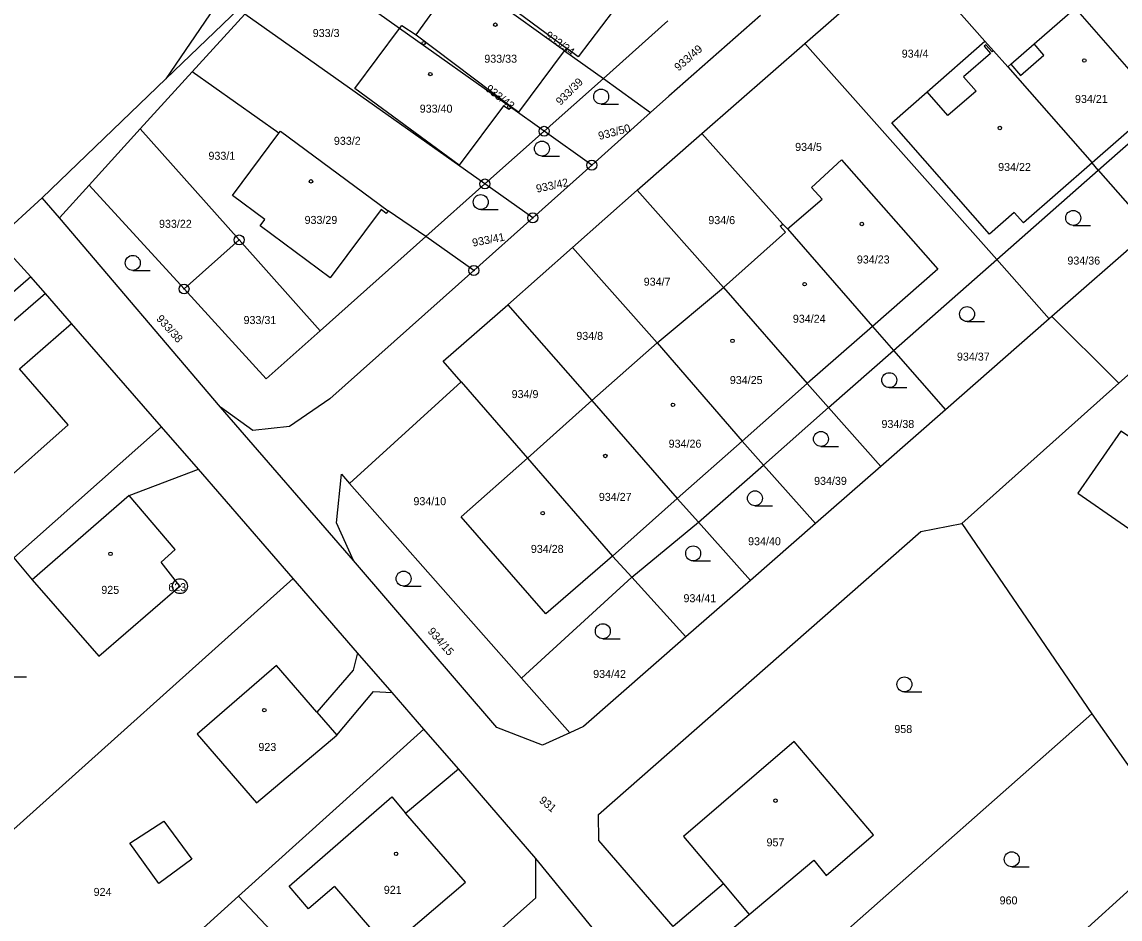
# Model space of a CAD drawing. Extents: x -587171 to -555306, y -1167727 to -1074732.
# Drawn here: x -560264.8 to -560154.7, y -1077555.8 to -1077465.8 of the extents above; entities that cross this region are included whole.
import ezdxf

# ---------------------------------------------------------------- set-up
doc = ezdxf.new("R2010")
doc.units = 0
for name, color, linetype in [('Hranice parcel', 7, 'Continuous'), ('Parcelní čísla', 7, 'Continuous'), ('Vnitřní kresba', 7, 'Continuous'), ('Značky bodu BP', 7, 'Continuous'), ('Značky budov', 7, 'Continuous'), ('Značky kultur', 7, 'Continuous')]:
    doc.layers.add(name, color=color, linetype=linetype)

msp = doc.modelspace()

# ---------------------------------------------------------------- linework, layer by layer
at = {"layer": 'Hranice parcel'}
for p, q in [((-560226.94, -1077466.44), (-560237.17, -1077459.16)), ((-560186.28, -1077467.93), (-560175.99, -1077458.92)), ((-560175.99, -1077458.92), (-560168.22, -1077467.71)), ((-560225.28, -1077467.06), (-560220.97, -1077461.08)), ((-560210.38, -1077468.68), (-560220.97, -1077461.08)), ((-560219.22, -1077461.72), (-560210.18, -1077468.42)), ((-560247.74, -1077470.8), (-560242.45, -1077464.98)), ((-560218.38, -1077482.04), (-560242.45, -1077464.98)), ((-560206.5, -1077471.46), (-560200.02, -1077465.68)), ((-560215.82, -1077474.34), (-560226.94, -1077466.44)), ((-560225.28, -1077467.06), (-560215.76, -1077474.25)), ((-560196.61, -1077476.96), (-560186.28, -1077467.93)), ((-560186.28, -1077467.93), (-560167.04, -1077489.63)), ((-560210.18, -1077468.42), (-560210.38, -1077468.68)), ((-560210.38, -1077468.68), (-560206.5, -1077471.46)), ((-560165.93, -1077470.29), (-560157.48, -1077479.93)), ((-560250.37, -1077471.48), (-560262.78, -1077483.42)), ((-560252.95, -1077476.52), (-560247.74, -1077470.8)), ((-560239.05, -1077476.93), (-560247.74, -1077470.8)), ((-560212.44, -1077476.75), (-560206.5, -1077471.46)), ((-560206.5, -1077471.46), (-560201.76, -1077474.87)), ((-560154.78, -1077502.03), (-560122.01, -1077472.74)), ((-560215.76, -1077474.25), (-560215.82, -1077474.34)), ((-560212.44, -1077476.75), (-560215.82, -1077474.34)), ((-560201.76, -1077474.87), (-560207.66, -1077480.15)), ((-560156.85, -1077480.65), (-560150.14, -1077474.73)), ((-560258.07, -1077482.16), (-560252.95, -1077476.52)), ((-560252.95, -1077476.52), (-560243.03, -1077487.66)), ((-560218.38, -1077482.04), (-560212.44, -1077476.75)), ((-560207.66, -1077480.15), (-560212.44, -1077476.75)), ((-560203.12, -1077482.67), (-560196.61, -1077476.96)), ((-560196.61, -1077476.96), (-560188.5, -1077486.06)), ((-560207.66, -1077480.15), (-560213.58, -1077485.44)), ((-560156.85, -1077480.65), (-560157.48, -1077479.93)), ((-560167.04, -1077489.63), (-560156.85, -1077480.65)), ((-560156.85, -1077480.65), (-560151.61, -1077486.65)), ((-560261.05, -1077485.45), (-560258.07, -1077482.16)), ((-560258.07, -1077482.16), (-560248.56, -1077492.58)), ((-560224.31, -1077487.32), (-560218.38, -1077482.04)), ((-560213.58, -1077485.44), (-560218.38, -1077482.04)), ((-560262.78, -1077483.42), (-560267.37, -1077487.58)), ((-560261.05, -1077485.45), (-560262.78, -1077483.42)), ((-560209.6, -1077488.41), (-560203.12, -1077482.67)), ((-560203.12, -1077482.67), (-560194.46, -1077492.43)), ((-560224.31, -1077487.32), (-560228.1, -1077484.74)), ((-560244.9, -1077504.45), (-560261.05, -1077485.45)), ((-560213.58, -1077485.44), (-560219.49, -1077490.72)), ((-560188.5, -1077486.06), (-560188.04, -1077486.53)), ((-560188.04, -1077486.53), (-560179.49, -1077496.34)), ((-560151.61, -1077486.65), (-560161.51, -1077495.35)), ((-560263.92, -1077491.36), (-560267.37, -1077487.58)), ((-560248.56, -1077492.58), (-560243.03, -1077487.66)), ((-560243.03, -1077487.66), (-560234.91, -1077496.77)), ((-560234.91, -1077496.77), (-560224.31, -1077487.32)), ((-560219.49, -1077490.72), (-560224.31, -1077487.32)), ((-560216.09, -1077494.16), (-560209.6, -1077488.41)), ((-560209.6, -1077488.41), (-560201.09, -1077497.99)), ((-560177.38, -1077498.75), (-560167.04, -1077489.63)), ((-560167.04, -1077489.63), (-560161.77, -1077495.57)), ((-560263.92, -1077491.36), (-560300.86, -1077523.32)), ((-560262.47, -1077493.02), (-560263.92, -1077491.36)), ((-560219.49, -1077490.72), (-560233.92, -1077503.62)), ((-560201.09, -1077497.99), (-560194.46, -1077492.43)), ((-560259.85, -1077496.04), (-560262.47, -1077493.02)), ((-560216.09, -1077494.16), (-560207.66, -1077503.77)), ((-560161.77, -1077495.57), (-560172.18, -1077504.7)), ((-560161.51, -1077495.35), (-560161.77, -1077495.57)), ((-560250.82, -1077506.4), (-560259.85, -1077496.04)), ((-560179.49, -1077496.34), (-560177.38, -1077498.75)), ((-560207.66, -1077503.77), (-560201.09, -1077497.99)), ((-560183.9, -1077504.49), (-560177.38, -1077498.75)), ((-560177.38, -1077498.75), (-560172.18, -1077504.7)), ((-560231.97, -1077512.1), (-560220.76, -1077501.91)), ((-560220.76, -1077501.91), (-560214.1, -1077509.55)), ((-560170.54, -1077516.12), (-560154.78, -1077502.03)), ((-560231.56, -1077519.83), (-560244.9, -1077504.45)), ((-560214.1, -1077509.55), (-560207.66, -1077503.77)), ((-560190.43, -1077510.25), (-560183.9, -1077504.49)), ((-560183.9, -1077504.49), (-560178.67, -1077510.39)), ((-560172.18, -1077504.7), (-560178.67, -1077510.39)), ((-560250.82, -1077506.4), (-560265.62, -1077519.56)), ((-560247.12, -1077510.67), (-560250.82, -1077506.4)), ((-560214.1, -1077509.55), (-560205.58, -1077519.4)), ((-560237.62, -1077521.64), (-560247.12, -1077510.67)), ((-560196.95, -1077516), (-560190.43, -1077510.25)), ((-560190.43, -1077510.25), (-560185.22, -1077516.13)), ((-560178.67, -1077510.39), (-560185.22, -1077516.13)), ((-560231.97, -1077512.1), (-560214.71, -1077531.65)), ((-560203.65, -1077521.52), (-560196.95, -1077516)), ((-560196.95, -1077516), (-560191.74, -1077521.84)), ((-560185.22, -1077516.13), (-560191.74, -1077521.84)), ((-560170.54, -1077516.12), (-560157.51, -1077535.21)), ((-560203.65, -1077521.52), (-560205.58, -1077519.4)), ((-560237.62, -1077521.64), (-560274.02, -1077554.33)), ((-560231.16, -1077529.09), (-560237.62, -1077521.64)), ((-560214.71, -1077531.65), (-560203.65, -1077521.52)), ((-560203.65, -1077521.52), (-560198.21, -1077527.51)), ((-560191.74, -1077521.84), (-560198.21, -1077527.51)), ((-560227.68, -1077533.09), (-560231.16, -1077529.09)), ((-560209.87, -1077537.13), (-560214.71, -1077531.65)), ((-560224.51, -1077536.75), (-560227.68, -1077533.09)), ((-560191.75, -1077565.49), (-560157.51, -1077535.21)), ((-560157.51, -1077535.21), (-560148.96, -1077547.42)), ((-560224.51, -1077536.75), (-560243.11, -1077553.53)), ((-560221.04, -1077540.75), (-560224.51, -1077536.75)), ((-560213.26, -1077549.74), (-560221.04, -1077540.75)), ((-560199.49, -1077556.57), (-560206.96, -1077547.95)), ((-560181.09, -1077577.69), (-560148.82, -1077548.43)), ((-560199.75, -1077566.27), (-560213.26, -1077549.74)), ((-560243.11, -1077553.53), (-560260.72, -1077569.43))]:
    msp.add_line(p, q, dxfattribs=at)
for points in [[(-560214.76, -1077410.16), (-560235.05, -1077451.08), (-560238.97, -1077460.52), (-560250.37, -1077471.48)], [(-560231.69, -1077442.28), (-560235.75, -1077449.99), (-560250.37, -1077471.48)], [(-560219.22, -1077461.72), (-560214.58, -1077455.47), (-560204.35, -1077463.08), (-560209.01, -1077469.29), (-560210.18, -1077468.42)], [(-560165.93, -1077470.29), (-560165.62, -1077470.03), (-560163.3, -1077467.99), (-560159.18, -1077464.39)], [(-560159.18, -1077464.39), (-560150.76, -1077474.02), (-560150.14, -1077474.73)], [(-560226.94, -1077466.44), (-560226.7, -1077466.12), (-560225.28, -1077467.06)], [(-560190.74, -1077465.12), (-560199.94, -1077473.24), (-560201.76, -1077474.87)], [(-560215.82, -1077474.34), (-560215.99, -1077474.58), (-560216.52, -1077474.2), (-560220.97, -1077480.14), (-560231.42, -1077472.47), (-560226.94, -1077466.44)], [(-560157.48, -1077479.93), (-560164.36, -1077485.95), (-560165.28, -1077484.91), (-560167.78, -1077487.09), (-560177.57, -1077475.9), (-560174.03, -1077472.79), (-560168.22, -1077467.71)], [(-560168.22, -1077467.71), (-560167.37, -1077468.66), (-560165.93, -1077470.29)], [(-560215.76, -1077474.25), (-560214.99, -1077474.83), (-560210.38, -1077468.68)], [(-560228.1, -1077484.74), (-560228.28, -1077484.99), (-560228.8, -1077484.6), (-560233.91, -1077491.47), (-560240.93, -1077486.23), (-560240.45, -1077485.61), (-560243.7, -1077483.2), (-560239.05, -1077476.93)], [(-560239.05, -1077476.93), (-560238.9, -1077476.73), (-560228.1, -1077484.74)], [(-560188.04, -1077486.53), (-560184.54, -1077483.57), (-560185.61, -1077482.4), (-560182.62, -1077479.63), (-560172.96, -1077490.59), (-560179.49, -1077496.34)], [(-560194.46, -1077492.43), (-560188.22, -1077486.88), (-560188.75, -1077486.27), (-560188.5, -1077486.06)], [(-560194.46, -1077492.43), (-560186.04, -1077502.08), (-560183.9, -1077504.49)], [(-560262.47, -1077493.02), (-560267.72, -1077497.56), (-560274.71, -1077503.79), (-560267.19, -1077512.45), (-560260.18, -1077506.22), (-560265.06, -1077500.61), (-560259.85, -1077496.04)], [(-560248.56, -1077492.58), (-560240.33, -1077501.59), (-560234.91, -1077496.77)], [(-560220.76, -1077501.91), (-560222.57, -1077499.83), (-560216.09, -1077494.16)], [(-560154.78, -1077502.03), (-560155.11, -1077501.7), (-560161.51, -1077495.35)], [(-560201.09, -1077497.99), (-560192.57, -1077507.84), (-560190.43, -1077510.25)], [(-560147.31, -1077502.53), (-560148.82, -1077501.54), (-560153.11, -1077507.82), (-560154.6, -1077506.84), (-560158.9, -1077513.07), (-560150.41, -1077518.96), (-560145.99, -1077512.72), (-560144.51, -1077513.73), (-560140.23, -1077507.47)], [(-560233.92, -1077503.62), (-560237.97, -1077506.39), (-560241.66, -1077506.79), (-560244.9, -1077504.45)], [(-560207.66, -1077503.77), (-560199.08, -1077513.62), (-560196.95, -1077516)], [(-560205.58, -1077519.4), (-560212.27, -1077525.17), (-560220.76, -1077515.46), (-560214.1, -1077509.55)], [(-560265.62, -1077519.56), (-560263.78, -1077521.77), (-560257.11, -1077529.45), (-560248.97, -1077522.41), (-560250.85, -1077520), (-560249.45, -1077518.72), (-560254.07, -1077513.3), (-560247.12, -1077510.67)], [(-560231.56, -1077519.83), (-560233.27, -1077516.04), (-560232.77, -1077511.18), (-560231.97, -1077512.1)], [(-560206.96, -1077547.95), (-560206.97, -1077545.34), (-560174.65, -1077516.92), (-560170.54, -1077516.12)], [(-560209.87, -1077537.13), (-560212.61, -1077538.36), (-560217.19, -1077536.61), (-560231.56, -1077519.83)], [(-560198.21, -1077527.51), (-560208.48, -1077536.51), (-560209.87, -1077537.13)], [(-560231.16, -1077529.09), (-560231.6, -1077530.83), (-560235.25, -1077535.05), (-560239.29, -1077530.38), (-560247.26, -1077537.26), (-560241.3, -1077544.14), (-560233.24, -1077537.37), (-560229.55, -1077532.97), (-560227.68, -1077533.09)], [(-560196.87, -1077559.58), (-560191.86, -1077555.36), (-560185.4, -1077549.92), (-560184.14, -1077551.46), (-560179.41, -1077547.36), (-560187.35, -1077537.99), (-560198.47, -1077547.52), (-560194.44, -1077552.3), (-560199.49, -1077556.57)], [(-560243.11, -1077553.53), (-560233.23, -1077563.99), (-560228.13, -1077558.76), (-560220.34, -1077552.13), (-560226.33, -1077545.19), (-560221.04, -1077540.75)], [(-560247.77, -1077584.47), (-560213.26, -1077553.69), (-560213.26, -1077549.74)]]:
    msp.add_lwpolyline(points, dxfattribs=at)
at = {"layer": 'Vnitřní kresba'}
for p, q in [((-560168.12, -1077468.06), (-560168.3, -1077468.22)), ((-560168.3, -1077468.22), (-560167.68, -1077468.93)), ((-560167.5, -1077468.77), (-560168.12, -1077468.06)), ((-560162.3, -1077469.12), (-560163.3, -1077467.99)), ((-560167.68, -1077468.93), (-560170.37, -1077471.28)), ((-560167.37, -1077468.66), (-560167.5, -1077468.77)), ((-560164.64, -1077471.16), (-560162.3, -1077469.12)), ((-560165.62, -1077470.03), (-560164.64, -1077471.16)), ((-560170.37, -1077471.28), (-560169.11, -1077472.71)), ((-560169.11, -1077472.71), (-560171.94, -1077475.18)), ((-560171.94, -1077475.18), (-560174.03, -1077472.79)), ((-560150.76, -1077474.02), (-560157.48, -1077479.93)), ((-560179.49, -1077496.34), (-560186.04, -1077502.08)), ((-560186.04, -1077502.08), (-560192.57, -1077507.84)), ((-560192.57, -1077507.84), (-560199.08, -1077513.62)), ((-560254.07, -1077513.3), (-560263.78, -1077521.77)), ((-560199.08, -1077513.62), (-560205.58, -1077519.4)), ((-560235.25, -1077535.05), (-560233.24, -1077537.37)), ((-560254.01, -1077548.22), (-560250.59, -1077546)), ((-560250.59, -1077546), (-560247.78, -1077549.81)), ((-560251.08, -1077552.25), (-560254.01, -1077548.22)), ((-560247.78, -1077549.81), (-560251.08, -1077552.25)), ((-560233.46, -1077552.54), (-560228.13, -1077558.76)), ((-560194.44, -1077552.3), (-560191.86, -1077555.36))]:
    msp.add_line(p, q, dxfattribs=at)
msp.add_lwpolyline([(-560233.46, -1077552.54), (-560236.08, -1077554.78), (-560238.01, -1077552.53), (-560227.73, -1077543.56), (-560226.33, -1077545.19)], dxfattribs=at)
at = {"layer": 'Značky bodu BP'}
for centre, radius in [((-560212.44, -1077476.75), 0.5), ((-560212.44, -1077476.75), 0.0303), ((-560207.66, -1077480.15), 0.5), ((-560207.66, -1077480.15), 0.0303), ((-560218.38, -1077482.04), 0.5), ((-560218.38, -1077482.04), 0.0303), ((-560213.58, -1077485.44), 0.5), ((-560213.58, -1077485.44), 0.0303), ((-560243.03, -1077487.66), 0.5), ((-560243.03, -1077487.66), 0.0303), ((-560219.49, -1077490.72), 0.5), ((-560219.49, -1077490.72), 0.0303), ((-560248.56, -1077492.58), 0.5), ((-560248.56, -1077492.58), 0.0303), ((-560248.97, -1077522.41), 0.75), ((-560248.97, -1077522.41), 0.03)]:
    msp.add_circle(centre, radius, dxfattribs=at)
at = {"layer": 'Značky budov'}
for centre in [(-560217.33, -1077466.05), (-560224.52, -1077467.9), (-560158.26, -1077469.65), (-560223.86, -1077471.01), (-560166.73, -1077476.42), (-560235.82, -1077481.78), (-560180.57, -1077486.06), (-560186.31, -1077492.1), (-560193.55, -1077497.79), (-560199.52, -1077504.21), (-560206.3, -1077509.34), (-560212.58, -1077515.08), (-560255.94, -1077519.16), (-560240.51, -1077534.86), (-560189.23, -1077543.94), (-560227.29, -1077549.27)]:
    msp.add_circle(centre, 0.175, dxfattribs=at)
at = {"layer": 'Značky kultur'}
for p, q in [((-560206.72, -1077474.02), (-560204.97, -1077474.02)), ((-560212.66, -1077479.24), (-560210.91, -1077479.24)), ((-560218.8, -1077484.61), (-560217.05, -1077484.61)), ((-560159.37, -1077486.2), (-560157.62, -1077486.2)), ((-560253.7, -1077490.71), (-560251.95, -1077490.71)), ((-560170.02, -1077495.85), (-560168.27, -1077495.85)), ((-560177.82, -1077502.48), (-560176.07, -1077502.48)), ((-560184.67, -1077508.38), (-560182.92, -1077508.38)), ((-560191.29, -1077514.34), (-560189.54, -1077514.34)), ((-560197.49, -1077519.87), (-560195.74, -1077519.87)), ((-560226.54, -1077522.4), (-560224.79, -1077522.4)), ((-560206.55, -1077527.68), (-560204.8, -1077527.68)), ((-560266.11, -1077531.52), (-560264.36, -1077531.52)), ((-560176.3, -1077533.02), (-560174.55, -1077533.02)), ((-560165.53, -1077550.57), (-560163.78, -1077550.57))]:
    msp.add_line(p, q, dxfattribs=at)
for centre in [(-560206.72, -1077473.27), (-560212.66, -1077478.49), (-560218.8, -1077483.86), (-560159.37, -1077485.45), (-560253.7, -1077489.96), (-560170.02, -1077495.1), (-560177.82, -1077501.73), (-560184.67, -1077507.63), (-560191.29, -1077513.59), (-560197.49, -1077519.12), (-560226.54, -1077521.65), (-560206.55, -1077526.93), (-560176.3, -1077532.27), (-560165.53, -1077549.82)]:
    msp.add_circle(centre, 0.75, dxfattribs=at)

# ---------------------------------------------------------------- texts
at = {"layer": 'Parcelní čísla'}
for s, p in [('933/3', (-560235.65, -1077467.29)), ('933/33', (-560218.44, -1077469.87)), ('934/4', (-560176.57, -1077469.36)), ('934/21', (-560159.19, -1077473.91)), ('933/40', (-560224.92, -1077474.88)), ('933/2', (-560233.53, -1077478.11)), ('934/5', (-560187.26, -1077478.72)), ('933/1', (-560246.11, -1077479.61)), ('934/22', (-560166.9, -1077480.74)), ('933/22', (-560251.07, -1077486.44)), ('933/29', (-560236.47, -1077486.05)), ('934/6', (-560195.97, -1077486.07)), ('934/23', (-560181.07, -1077490.02)), ('934/36', (-560159.95, -1077490.13)), ('934/7', (-560202.45, -1077492.25)), ('933/31', (-560242.59, -1077496.1)), ('934/24', (-560187.49, -1077495.97)), ('934/8', (-560209.21, -1077497.69)), ('934/37', (-560171.03, -1077499.77)), ('934/25', (-560193.81, -1077502.12)), ('934/9', (-560215.7, -1077503.53)), ('934/38', (-560178.6, -1077506.53)), ('934/26', (-560199.95, -1077508.51)), ('934/39', (-560185.36, -1077512.24)), ('934/10', (-560225.55, -1077514.28)), ('934/27', (-560206.95, -1077513.85)), ('934/40', (-560191.98, -1077518.3)), ('934/28', (-560213.77, -1077519.07)), ('925', (-560256.86, -1077523.18)), ('934/41', (-560198.46, -1077524.02)), ('934/42', (-560207.52, -1077531.62)), ('958', (-560177.31, -1077537.15)), ('923', (-560241.1, -1077538.95)), ('957', (-560190.13, -1077548.52)), ('924', (-560257.63, -1077553.5)), ('921', (-560228.52, -1077553.29)), ('960', (-560166.75, -1077554.35))]:
    msp.add_text(s, height=0.803, dxfattribs=at).set_placement(p)
for s, rotation, p in [('933/34', 324, (-560212.41, -1077467.29)), ('933/49', 41, (-560198.96, -1077470.76)), ('933/39', 45, (-560210.79, -1077474.2)), ('933/43', 322, (-560218.39, -1077472.62)), ('933/50', 15, (-560206.89, -1077477.63)), ('933/42', 12, (-560213.16, -1077482.92)), ('933/41', 11, (-560219.57, -1077488.34)), ('933/38', 312, (-560251.4, -1077495.61)), ('934/15', 311, (-560224.17, -1077526.98)), ('931', 320, (-560213.01, -1077544.02))]:
    msp.add_text(s, height=0.803, rotation=rotation, dxfattribs=at).set_placement(p)
at = {"layer": 'Značky bodu BP'}
msp.add_text('623', height=0.803, dxfattribs=at).set_placement((-560250.14, -1077522.91))

doc.saveas('drawing.dxf')
